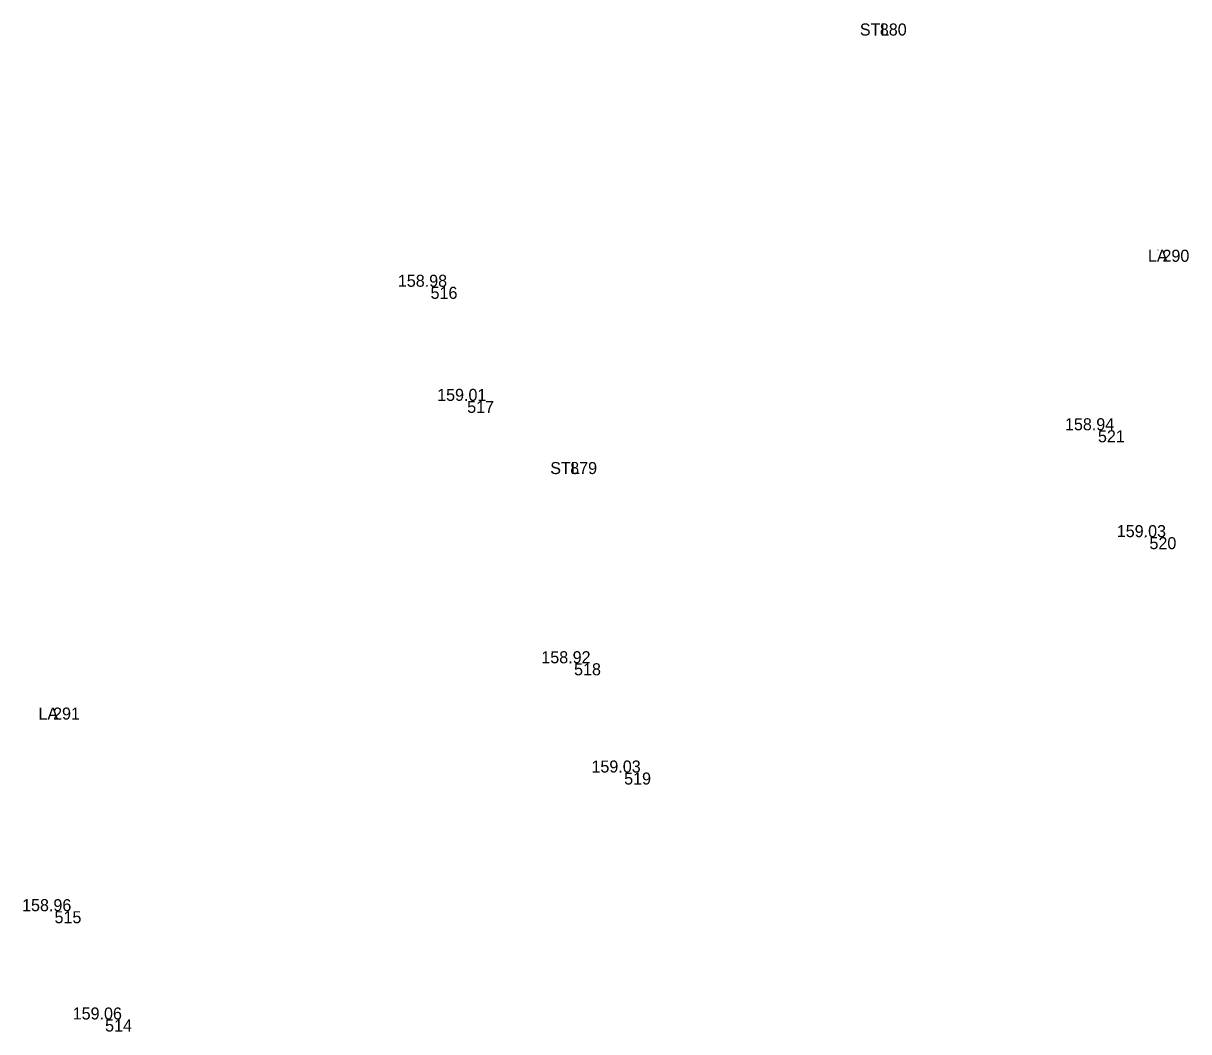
# Model space of a CAD drawing. Extents: x -583198 to -582878, y -1211024 to -1210637.
# Drawn here: x -583061.89 to -583037.68, y -1210888.04 to -1210867.1 of the extents above; entities that cross this region are included whole.
import ezdxf

# ---------------------------------------------------------------- set-up
doc = ezdxf.new("R2010")
doc.units = 0
for name, color, linetype in [('1   Kódy', 7, 'Continuous'), ('4   Body podrobné', 7, 'Continuous'), ('5   Body podrobné - čísla', 7, 'Continuous'), ('6   Body podrobné - výšky', 7, 'Continuous')]:
    doc.layers.add(name, color=color, linetype=linetype)

msp = doc.modelspace()

# ---------------------------------------------------------------- linework, layer by layer
at = {"layer": '4   Body podrobné'}
for p, q in [((-583044.19, -1210867.1), (-583044.189, -1210867.1)), ((-583038.32, -1210871.8), (-583038.319, -1210871.8)), ((-583053.52, -1210872.57), (-583053.519, -1210872.57)), ((-583052.76, -1210874.94), (-583052.759, -1210874.94)), ((-583039.66, -1210875.55), (-583039.659, -1210875.55)), ((-583050.62, -1210876.21), (-583050.619, -1210876.21)), ((-583038.59, -1210877.77), (-583038.589, -1210877.77)), ((-583050.54, -1210880.39), (-583050.539, -1210880.39)), ((-583061.36, -1210881.31), (-583061.359, -1210881.31)), ((-583049.5, -1210882.66), (-583049.499, -1210882.66)), ((-583061.33, -1210885.54), (-583061.329, -1210885.54)), ((-583060.28, -1210887.79), (-583060.279, -1210887.79))]:
    msp.add_line(p, q, dxfattribs=at)

# ---------------------------------------------------------------- texts
at = {"layer": '1   Kódy'}
for s, p in [('STL', (-583044.512, -1210867.35)), ('LA', (-583038.53, -1210872.05)), ('STL', (-583050.942, -1210876.46)), ('LA', (-583061.57, -1210881.56))]:
    msp.add_text(s, height=0.25, dxfattribs=at).set_placement(p)
at = {"layer": '5   Body podrobné - čísla'}
for s, p in [(' 880', (-583044.19, -1210867.35)), (' 290', (-583038.32, -1210872.05)), (' 516', (-583053.52, -1210872.82)), (' 517', (-583052.76, -1210875.19)), (' 521', (-583039.66, -1210875.8)), (' 879', (-583050.62, -1210876.46)), (' 520', (-583038.59, -1210878.02)), (' 518', (-583050.54, -1210880.64)), (' 291', (-583061.36, -1210881.56)), (' 519', (-583049.5, -1210882.91)), (' 515', (-583061.33, -1210885.79)), (' 514', (-583060.28, -1210888.04))]:
    msp.add_text(s, height=0.25, dxfattribs=at).set_placement(p)
at = {"layer": '6   Body podrobné - výšky'}
for s, p in [('158.98', (-583054.107, -1210872.57)), ('159.01', (-583053.291, -1210874.94)), ('158.94', (-583040.252, -1210875.55)), ('159.03', (-583039.176, -1210877.77)), ('158.92', (-583051.127, -1210880.39)), ('159.03', (-583050.086, -1210882.66)), ('158.96', (-583061.911, -1210885.54)), ('159.06', (-583060.86, -1210887.79))]:
    msp.add_text(s, height=0.25, dxfattribs=at).set_placement(p)

doc.saveas('drawing.dxf')
